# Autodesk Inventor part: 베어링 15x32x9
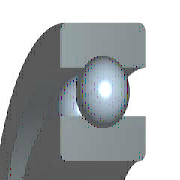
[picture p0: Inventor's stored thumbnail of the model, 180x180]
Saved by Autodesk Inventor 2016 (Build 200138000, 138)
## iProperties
IsCustomPart: 0
Created: 2012-02
Part Number: 베어링 15x32x9
Material: 강철, 연강
Description: 깊은 그루브 볼 베어링
Document SubType Name: Modeling
Standard: KS B 2023
Designer: mduedu
Standards Organization: KS
Language: ko-KR
Size Designation: 6002 - 15 x 32 x 9
Categories: <MemberInstance><Categories><Category DisplayName="샤프트 부품" InternalName="7f7aeb1f-a693-4053-b835-cee3144e0d98" Mnemonic="SHFT"><Category DisplayName="베어링" Inter
Density: 1 g/cm^3
Appearance: 노란색
Author: mduedu
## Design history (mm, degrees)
sketch "스케치" dims "d0" = 4.42 (= -0.26 x WD + 0.26 x BD)
  geometry: L1 (2.29, 11.75)-(6.71, 11.75); L2 (4.5, 11.75)-(4.5, 9.54); L3 (4.5, 11.75)-(4.5, 13.96); L4 (2.858, 10.271)-(0, 10.271); L5 (0, 7.5)-(9, 7.5); L6 (2.858, 13.229)-(0, 13.229); L7 (0, 16)-(9, 16); L8 (9, 7.5)-(9, 10.271); L9 (6.142, 10.271)-(9, 10.271); L10 (6.142, 13.229)-(9, 13.229); L11 (9, 16)-(9, 13.229); L12 (-1.4, 0)-(8.4, 0) reference; L13 (0, -0.3)-(0, 5.3) reference
  constraints: 22 end point, 4 point on line, 2 collinear, 2 perpendicular, 2 symmetric about line, 1 midpoint, 1 parallel, 14 other
  dimensions: "d9" = 15 diameter of L5 L12 (= WD); "d11" = 32 diameter of L7 L12 (= BD); "d12" = 9 distance between parallel lines of L8 L13 (= KB); "d13" = 20.542 diameter of L9 L12 (= 0.326 x BD + 0.674 x WD)
revolve "본체" stored, may be unused: angle "d6" = 90 deg
revolve "볼" stored, may be unused: angle "d7" = 90 deg
pattern_circular "IDS_ARRAYBALL[SIMPL:T]" dims angle "d3" = 360 deg
body "Solid1"
fillet "모깎기1" dims "d1" = 0.3 (= KRS)
other parameters: "WD" = 15 [user parameter; used in 5 equation terms], "BD" = 32 [user parameter; used in 5 equation terms], "KB" = 9 [user parameter; used in 1 equation term], "KRS" = 0.3 [user parameter; used in 1 equation term], "d4" = 0, "d5" = 0, "d8" = 0, "d14" = 0, "d15" = 0, "BBA" = 0 [user parameter], "BC0" = 2850000 [user parameter], "BC" = 5590000 [user parameter], "BR" = 16 (= 0.5 x BD) [user parameter], "WR" = 7.5 (= 0.5 x WD) [user parameter]
